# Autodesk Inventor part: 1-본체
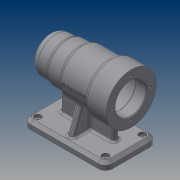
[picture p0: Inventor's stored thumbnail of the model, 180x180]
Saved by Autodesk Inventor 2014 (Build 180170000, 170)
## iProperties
Created: 2016-06
Part Number: 1-본체
Material: 일반
Document SubType Name: Modeling
Designer: SEC
Density: 1 g/cm^3
Appearance: 기본값
Author: SEC
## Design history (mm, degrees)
sketch "스케치1"
  geometry: L1 (-56, 0)-(56, 0); L2 (56, 21)-(56, 34); L3 (56, 34)-(28, 34); L4 (28, 34)-(28, 30); L5 (28, 30)-(-11, 30); L6 (-11, 30)-(-11, 27); L7 (-11, 27)-(-31, 27); L8 (-31, 27)-(-31, 25); L9 (-31, 25)-(-56, 25); L10 (-56, 25)-(-56, 0); L11 (56, 21)-(41, 21); L12 (41, 21)-(41, 24); L13 (41, 24)-(-13, 24); L14 (-13, 24)-(-13, 21); L15 (-13, 21)-(-25, 21); L16 (-25, 21)-(-25, 17.5); L17 (-25, 17.5)-(-43, 17.5); L18 (-43, 17.5)-(-43, 16); L19 (-43, 16)-(-47, 16); L20 (-47, 16)-(-47, 10.5); L21 (-47, 10.5)-(-50, 10.5); L22 (-50, 10.5)-(-50, 0); 2 further points
  constraints: 44 end point, 12 parallel, 9 perpendicular, 1 coincident, 1 horizontal, 1 midpoint, 1 point on line, 1 vertical alignment
  dimensions: "d0" = 112 distance of L1.start L1.end; "d1" = 68 diameter of L3 L1; "d2" = 50 diameter of L9 L1; "d3" = 54 diameter of L7 L1; "d4" = 60 diameter of L5 L1; "d5" = 84 horizontal distance of L3.end L9.end; "d6" = 45 horizontal distance of L9.end L5.end; "d7" = 25 horizontal distance of L9.end L7.end; "d9" = 42 diameter of L11 L1; "d10" = 48 diameter of L13 L1; "d11" = 42 diameter of L15 L1; "d12" = 35 diameter of L17 L1; "d13" = 32 diameter of L19 L1; "d14" = 21 diameter of L21 L1; "d15" = 15 distance of L2.start L11.end; "d16" = 54 distance of L12.end L13.end; "d17" = 12 distance of L14.end L15.end; "d18" = 18 distance of L16.end L17.end; "d19" = 4 distance of L18.end L19.end; "d20" = 3 distance of L20.end L21.end
revolve "회전1" sketch "스케치1" stored, may be unused: angle "d8" = 90 deg
node "작업 평면1"
sketch "스케치2"
  geometry: L1 (56, -35)-(-56, -35); L2 (-56, -35)-(-56, 35); L3 (-56, 35)-(56, 35); L4 (56, 35)-(56, -35); L5 (56, -35)-(-56, 35); L6 (-56, -35)-(56, 35); 1 further point
  constraints: 12 end point, 2 midpoint, 2 parallel, 1 horizontal, 1 perpendicular
  dimensions: "d22" = 112 distance of L2.end L3.end; "d23" = 70 distance of L3.end L1.start
extrude "돌출1" join sketch "스케치2" distance "d24" = 10; taper "d25" = 0 deg
node "작업 평면4"
node "작업 평면5"
sketch "스케치10"
  geometry: 2 further points
  constraints: 1 vertical alignment
  dimensions: "d54" = 26 distance of point (0, 26) point (0, 0)
hole "구멍1" sketch "스케치10" at (0, 26) diameter "d55" = 3.242; stored, may be unused: countersink angle "d59" = 90 deg, drill point angle "d61" = 118 deg; dims "d56" = 8, "d57" = 4, "d58" = 2, "d60" = 10
fillet "모깎기1" dims "d65" = 10
sketch "스케치12"
  geometry: 2 further points
  dimensions: "d67" = 46 horizontal distance of point (-46, 25) point (0, 0); "d68" = 25 vertical distance of point (-46, 25) point (0, 0)
hole "구멍2" sketch "스케치12" at (-46, 25) diameter "d69" = 5; stored, may be unused: countersink angle "d73" = 90 deg, drill point angle "d75" = 0 deg; dims "d70" = 8, "d71" = 9, "d72" = 4, "d74" = 10
fillet "모깎기2" dims "d89" = 0.3
fillet "모깎기3" dims "d90" = 3
fillet "모깎기6" dims "d93" = 10
chamfer "모따기2" distance "d94" = 1; stored, may be unused: second distance "d95" = 2, angle "d96" = 45 deg
chamfer "모따기3" distance "d98" = 4; stored, may be unused: second distance "d99" = 2, angle "d100" = 45 deg
node "작업 평면9"
sketch "스케치15"
  geometry: L1 (0, 10)-(50, 10) reference; L2 (9.491, 44.32)-(-3, 10); L3 (40.509, 44.32)-(53, 10); L4 (60, 6)-(60, 0) reference; L5 (-10, 0)-(-10, 6) reference; L6 (-3, 10)-(53, 10); A1 r 30 centre (25, 70) between (9.491, 44.32) and (40.509, 44.32) reference; 1 further point
  constraints: 6 end point, 2 point on circle, 2 point on line, 1 collinear
  dimensions: "d103" = 110 deg angle of L1 L3; "d104" = 7 distance from line of L3.end L4; "d105" = 110 deg angle of L1 L2; "d106" = 7 distance from line of L2.end L5
extrude "돌출4" join sketch "스케치15" stored distance "d107" = 8; taper "d108" = 0 deg
node "작업 평면10"
sketch "스케치16"
  geometry: L1 (18, 36)-(-10, 36) reference; L2 (0, 10)-(92, 10) reference; L3 (10, 10)-(10, 36); L4 (-10, 0)-(-10, 6) reference; 1 further point
  constraints: 2 end point, 2 point on line, 1 perpendicular
  dimensions: "d109" = 20 distance between parallel lines of L4 L3
feature "리브3" sketch "스케치16" dims "d110" = 1, "d111" = 8, "d112" = 0, "d113" = 0, "d114" = 1, "d115" = 1
sketch "스케치17"
  geometry: L1 (92, 45)-(77, 45) reference; L2 (0, 10)-(92, 10) reference; L3 (82, 10)-(82, 45); L4 (102, 6)-(102, 0) reference; 1 further point
  constraints: 2 end point, 2 point on line, 1 perpendicular
  dimensions: "d116" = 20 distance between parallel lines of L3 L4
feature "리브4" sketch "스케치17" dims "d117" = 1, "d118" = 8, "d119" = 0, "d120" = 0, "d121" = 1, "d122" = 1
fillet "모깎기10" dims "d123" = 3
fillet "모깎기11" dims "d124" = 3
fillet "모깎기12" dims "d125" = 3
fillet "모깎기13" dims "d126" = 3
fillet "모깎기14" dims "d127" = 3
node "작업 평면11"
node "작업 평면13"
  node "작업 평면12"
sketch "스케치18"
  geometry: L1 (-17.092, -4.288)-(16.092, -4.288); L2 (16.092, -4.288)-(16.092, 4.288); L3 (16.092, 4.288)-(-17.092, 4.288); L4 (-17.092, 4.288)-(-17.092, -4.288); L5 (47.5, -34)-(47.5, 34) reference; 3 further points
  constraints: 2 midpoint, 1 horizontal alignment, 2 other
  dimensions: "d130" = 48 distance from line of point (-0.5, -4.288) L5; "d131" = 33.18318 distance of L2.end L3.end; "d132" = 8.57672 distance of L3.end L1.start; "d133" = 4.28836 vertical distance of point (16.092, 0) point (-0.5, -4.288)
extrude "돌출5" join sketch "스케치18" stored distance "d134" = 8; taper "d135" = 0 deg
node "솔리드1"
pattern_circular "원형 패턴1" dims angle "d63" = 360 deg
pattern_linear "직사각형 패턴1" dims "d78" = 92
other parameters: "d128" = 0, "d129" = 0.5
